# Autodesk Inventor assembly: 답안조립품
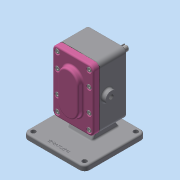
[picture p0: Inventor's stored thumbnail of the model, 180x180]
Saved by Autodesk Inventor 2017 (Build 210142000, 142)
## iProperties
Part Number: 답안조립품
Material: 일반
Document SubType Name: Assembly
Designer: MRC
Author: MRC
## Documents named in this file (11)
- C:\Users\MRC\Desktop\700407V1059\답안조립품.iam
- C:\Users\MRC\Desktop\700407V1059\본체.ipt
- C:\Users\MRC\Desktop\700407V1059\개스킷.ipt
- C:\Users\MRC\Desktop\700407V1059\메인축.ipt
- C:\Users\MRC\Desktop\700407V1059\베어링부시.ipt
- C:\Users\MRC\Desktop\700407V1059\볼트 M5.ipt
- C:\Users\MRC\Desktop\700407V1059\서브축.ipt
- C:\Users\MRC\Desktop\700407V1059\스퍼기어.ipt
- C:\Users\MRC\Desktop\700407V1059\오일 실 16 28 7.ipt
- C:\Users\MRC\Desktop\700407V1059\커버.ipt
- C:\Users\MRC\Desktop\700407V1059\키 6 x 6 x 18.ipt
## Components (1 placed, 1 different names)
1. 개스킷:1
